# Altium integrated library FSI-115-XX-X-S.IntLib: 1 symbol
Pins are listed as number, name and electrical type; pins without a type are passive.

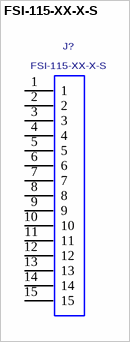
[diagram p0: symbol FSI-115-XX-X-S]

## FSI-115-XX-X-S
designator J?
Single Element Interface, Surface Mount, Threaded Insert, 1mm Pitch, 15 Pins.; MANUFACTURER: SAMTEC
footprint FSI-115-XX-X-S
pins: 1, 2, 3, 4, 5, 6, 7, 8, 9, 10, 11, 12, 13, 14, 15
